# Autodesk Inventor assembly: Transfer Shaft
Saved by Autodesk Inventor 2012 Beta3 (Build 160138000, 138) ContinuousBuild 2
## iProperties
Created: 2011-01
Part Number: Transfer Shaft
Document SubType Name: Assembly
Designer: Beta-8540w
ClientObjectVersion: 1
Author: Beta-8540w
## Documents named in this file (2)
- C:\Inventor 2012 Essentials\Assemblies\Chapter 8\Design Accelerators\Shaft c8-03.iam
- C:\Inventor 2012 Essentials\Assemblies\Chapter 8\Design Accelerators\Shaft c8-03.ipt
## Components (1 placed, 1 different names)
1. Transfer Shaft:1
